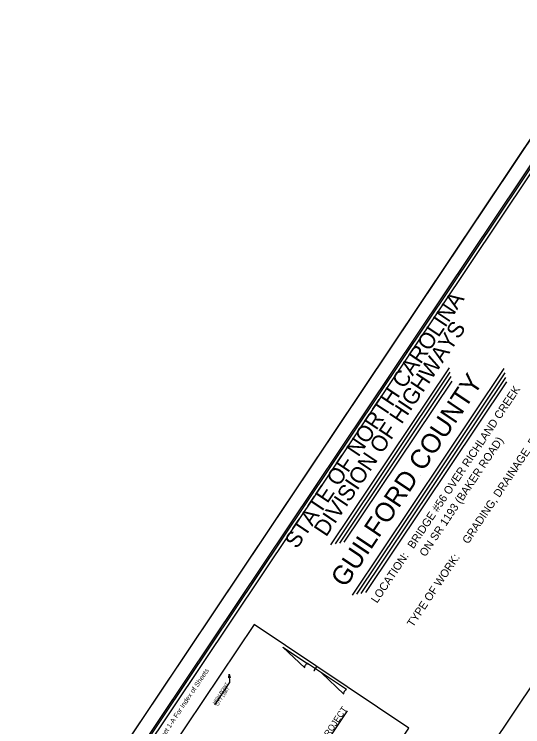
# Model space of a CAD drawing. Extents: x 1715610 to 1720914, y 798298 to 802505.
# Drawn here: x 1715998 to 1717190, y 800836 to 802505 of the extents above; entities that cross this region are included whole.
import ezdxf

# ---------------------------------------------------------------- set-up
doc = ezdxf.new("R2010")
doc.units = 0
for name, color, linetype in [('Prop DSN Text', 7, 'Continuous'), ('Prop North Arrow for Plan Sheets CELL', 7, 'Continuous'), ('Prop Terminator CELL', 7, 'Continuous'), ('Sheet Cutting Line CELL', 7, 'Continuous'), ('Sheet Data Field CELL', 7, 'Continuous'), ('Sheet Plot Border Inside CELL', 7, 'Continuous'), ('Sheet Plot Border Outside CELL', 7, 'Continuous'), ('Sheet Title CELL', 7, 'Continuous'), ('Sheet Title Data Points CELL', 7, 'Continuous')]:
    doc.layers.add(name, color=color, linetype=linetype)

msp = doc.modelspace()

# ---------------------------------------------------------------- linework, layer by layer
at = {"layer": 'Prop DSN Text'}
for p, q in [((1716502, 800959.1), (1716503, 800938.9)), ((1716468.4, 800887.2), (1716503, 800938.9)), ((1716714.3, 800776.4), (1716778.9, 800872.9))]:
    msp.add_line(p, q, dxfattribs=at)
for points in [[(1717114.5, 800787.1), (1717648.2, 801584.4), (1717980.5, 801362), (1717446.8, 800564.7)], [(1716644.3, 800417), (1716922.5, 800832.7), (1716560.2, 801075.1), (1716282, 800659.5)]]:
    msp.add_lwpolyline(points, close=True, dxfattribs=at)
at = {"layer": 'Prop North Arrow for Plan Sheets CELL'}
for p, q in [((1716628, 801022.6), (1716627.9, 801022.5)), ((1716628, 801022.6), (1716627.9, 801022.5)), ((1716678.9, 800973.6), (1716627.9, 801022.5)), ((1716628, 801022.6), (1716687.6, 800982.7)), ((1716718.5, 800962), (1716685.8, 800983.9)), ((1716687.6, 800982.7), (1716685.9, 800983.8)), ((1716700.7, 800966.7), (1716700.6, 800966.6)), ((1716700.7, 800966.8), (1716707.4, 800976.7)), ((1716703.6, 800971.1), (1716700.7, 800966.7)), ((1716718.5, 800962), (1716770.4, 800912.2)), ((1716777.2, 800922.8), (1716718.5, 800962))]:
    msp.add_line(p, q, dxfattribs=at)
for centre, start_param, end_param in [((1716682.9, 800978.4), 0.216388, 2.908219), ((1716774.1, 800917.3), 0.201328, 3.141593)]:
    msp.add_ellipse(centre, major_axis=(3.57, 5.25), ratio=0.461098, start_param=start_param, end_param=end_param, dxfattribs=at)
at = {"layer": 'Prop Terminator CELL'}
msp.add_lwpolyline([(1716500.9, 800950), (1716502, 800959.1), (1716504.1, 800950.2), (1716502.4, 800951.2)], close=True, dxfattribs=at)
at = {"layer": 'Sheet Cutting Line CELL'}
msp.add_line((1715998.5, 800406), (1717403.5, 802505.2), dxfattribs=at)
at = {"layer": 'Sheet Plot Border Inside CELL'}
msp.add_lwpolyline([(1717352.6, 799523.2), (1718743, 801600.5), (1717427.7, 802480.8), (1716037.3, 800403.5)], close=True, dxfattribs=at)
at = {"layer": 'Sheet Plot Border Outside CELL'}
msp.add_lwpolyline([(1717403.5, 802505.2), (1715998.5, 800406), (1717369.7, 799488.2), (1718774.7, 801587.4)], close=True, dxfattribs=at)
at = {"layer": 'Sheet Title CELL'}
for p, q in [((1716740.3, 801262.1), (1717018, 801676.9)), ((1716750.7, 801264.2), (1717020, 801666.5)), ((1716790.7, 801144.2), (1717146.1, 801675.2)), ((1716761.2, 801266.2), (1717022.1, 801656.1)), ((1716801.1, 801146.3), (1717148.2, 801664.8)), ((1716811.5, 801148.3), (1717150.2, 801654.4)), ((1716771.6, 801268.3), (1717024.1, 801645.7)), ((1716821.9, 801150.4), (1717152.3, 801644))]:
    msp.add_line(p, q, dxfattribs=at)
for points in [[(1717412.1, 802450.7), (1716177.3, 800605.8)], [(1717414.2, 802440.3), (1716229.5, 800670.2)]]:
    msp.add_lwpolyline(points, dxfattribs=at)
at = {"layer": 'Sheet Title Data Points CELL'}
for p, q in [((1717119, 801528.4), (1717119, 801528.4)), ((1716951.1, 801424.1), (1716951.1, 801424.1))]:
    msp.add_line(p, q, dxfattribs=at)

# ---------------------------------------------------------------- texts
at = {"layer": 'Prop DSN Text'}
for s, height, rotation, p in [('HIGH POINT', 7.13, 56.7857, (1716468.3, 800888.2)), ('CITY LIMIT', 7.13, 56.7857, (1716476, 800883.2)), ('PROJECT ', 14.7, 56.2051, (1716728.1, 800800.7))]:
    msp.add_text(s, height=height, rotation=rotation, dxfattribs=at).set_placement(p)
at = {"layer": 'Sheet Data Field CELL'}
for s, height, p in [('GRADING, DRAINAGE, PAVING, AND STRUCTURE', 18.75, (1717062.1, 801262.6)), ('GUILFORD COUNTY', 45, (1716774.2, 801159.8)), ('BRIDGE #56 OVER RICHLAND CREEK', 18.75, (1716933.7, 801251.5)), ('ON SR 1193 (BAKER ROAD)', 18.75, (1716961.7, 801232.7))]:
    msp.add_text(s, height=height, rotation=56.2051, dxfattribs=at).set_placement(p)
at = {"layer": 'Sheet Title CELL'}
for s, height, p in [('STATE OF NORTH CAROLINA', 37.5, (1716660.7, 801250.8)), ('DIVISION OF HIGHWAYS', 37.5, (1716729.1, 801278.9)), ('LOCATION: ', 18.75, (1716848.4, 801124)), ('TYPE OF WORK:', 18.75, (1716932.5, 801067.7)), ('See Sheet 1-A For Index of Sheets', 11.25, (1716321.3, 800767.7))]:
    msp.add_text(s, height=height, rotation=56.2051, dxfattribs=at).set_placement(p)

doc.saveas('drawing.dxf')
